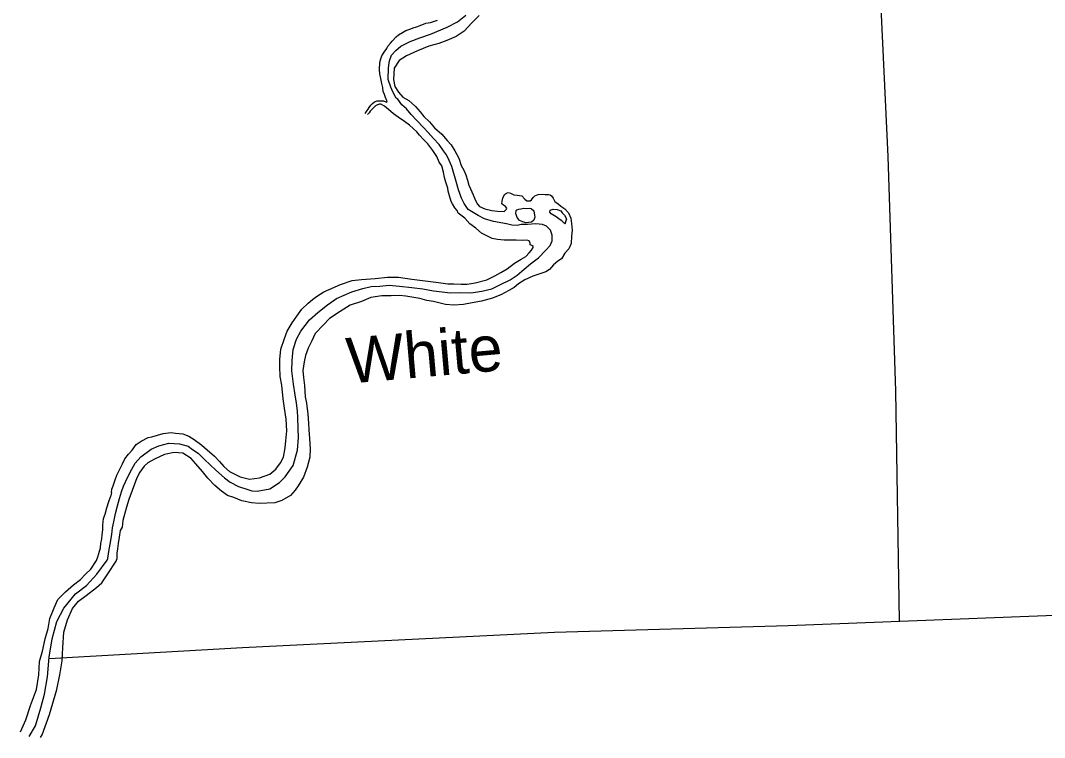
# Model space of a CAD drawing. Extents: x -939622 to -934222, y 1383701 to 1385301.
# Drawn here: x -935921.64 to -935886.1, y 1383819.87 to 1383844.76 of the extents above; entities that cross this region are included whole.
import ezdxf

# ---------------------------------------------------------------- set-up
doc = ezdxf.new("R2010")
doc.units = 0
for name, color, linetype in [('Level 2', 7, 'Continuous'), ('Level 7', 7, 'Continuous'), ('Level 9', 7, 'Continuous')]:
    doc.layers.add(name, color=color, linetype=linetype)

msp = doc.modelspace()

# ---------------------------------------------------------------- linework, layer by layer
at = {"layer": 'Level 2'}
for points in [[(-935907.297, 1383840.655), (-935907.483, 1383840.867), (-935907.641, 1383841.031), (-935907.891, 1383841.295), (-935908.08, 1383841.497), (-935908.241, 1383841.688), (-935908.398, 1383841.828), (-935908.539, 1383842.02), (-935908.594, 1383842.066), (-935908.714, 1383842.277), (-935908.782, 1383842.446), (-935908.873, 1383842.711), (-935908.869, 1383843.115), (-935908.831, 1383843.353), (-935908.759, 1383843.548), (-935908.613, 1383843.711), (-935908.431, 1383843.864), (-935908.112, 1383844.023), (-935907.777, 1383844.152), (-935907.402, 1383844.277), (-935906.824, 1383844.522), (-935906.466, 1383844.706), (-935906.185, 1383844.943)], [(-935918.608, 1383826.091), (-935918.597, 1383826.172), (-935918.568, 1383826.326), (-935918.519, 1383826.589), (-935918.468, 1383826.925), (-935918.441, 1383827.148), (-935918.393, 1383827.354), (-935918.342, 1383827.65), (-935918.271, 1383827.914), (-935918.203, 1383828.171), (-935918.129, 1383828.405), (-935918.059, 1383828.596), (-935917.912, 1383828.925), (-935917.776, 1383829.185), (-935917.653, 1383829.399), (-935917.455, 1383829.615), (-935917.102, 1383829.886), (-935916.83, 1383830.002), (-935916.487, 1383830.093), (-935916.117, 1383830.07), (-935915.821, 1383829.979), (-935915.668, 1383829.872), (-935915.475, 1383829.742), (-935915.256, 1383829.522), (-935914.862, 1383829.157), (-935914.557, 1383828.883), (-935914.358, 1383828.738), (-935914.071, 1383828.586), (-935913.744, 1383828.478), (-935913.602, 1383828.44), (-935913.428, 1383828.427), (-935912.986, 1383828.505), (-935912.644, 1383828.728), (-935912.452, 1383828.92), (-935912.175, 1383829.319), (-935912.019, 1383829.843), (-935911.983, 1383830.29), (-935912.001, 1383830.599), (-935912.011, 1383830.978), (-935912.018, 1383831.212), (-935912.058, 1383831.476), (-935912.109, 1383831.769), (-935912.161, 1383832.135), (-935912.219, 1383832.599), (-935912.208, 1383832.963), (-935912.168, 1383833.344), (-935912.052, 1383833.693), (-935911.907, 1383833.973), (-935911.609, 1383834.367), (-935911.313, 1383834.625), (-935910.981, 1383834.886), (-935910.666, 1383835.103), (-935910.133, 1383835.34), (-935909.752, 1383835.456), (-935909.466, 1383835.524), (-935909.169, 1383835.538), (-935908.846, 1383835.571), (-935908.479, 1383835.542), (-935908.058, 1383835.485), (-935907.676, 1383835.444), (-935907.305, 1383835.379), (-935907.004, 1383835.343), (-935906.721, 1383835.311), (-935906.391, 1383835.314), (-935906.012, 1383835.301), (-935905.627, 1383835.36), (-935905.284, 1383835.441), (-935905, 1383835.585), (-935904.642, 1383835.76), (-935904.394, 1383835.917), (-935904.151, 1383836.128), (-935903.94, 1383836.312), (-935903.661, 1383836.524), (-935903.402, 1383836.784), (-935903.256, 1383836.95), (-935903.186, 1383837.115), (-935903.182, 1383837.304), (-935903.241, 1383837.477), (-935903.377, 1383837.618), (-935903.523, 1383837.677), (-935903.754, 1383837.698), (-935904.036, 1383837.678), (-935904.264, 1383837.671), (-935904.404, 1383837.637), (-935904.581, 1383837.648), (-935904.768, 1383837.694), (-935905.224, 1383837.777), (-935905.536, 1383837.874), (-935905.755, 1383837.988), (-935906.097, 1383838.195), (-935906.241, 1383838.408), (-935906.336, 1383838.589), (-935906.437, 1383838.881), (-935906.511, 1383839.167), (-935906.62, 1383839.528), (-935906.67, 1383839.686), (-935906.757, 1383839.9), (-935906.846, 1383840.099), (-935906.961, 1383840.232), (-935907.102, 1383840.45), (-935907.297, 1383840.655)], [(-935921.334, 1383819.907), (-935921.12, 1383820.279), (-935920.93, 1383820.903), (-935920.805, 1383821.376), (-935920.699, 1383821.977), (-935920.64, 1383822.661), (-935920.532, 1383823.296), (-935920.371, 1383823.896), (-935920.132, 1383824.36), (-935919.732, 1383824.858), (-935919.341, 1383825.152), (-935918.982, 1383825.541), (-935918.633, 1383826.031)], [(-935918.633, 1383826.031), (-935918.608, 1383826.091)], [(-935913.934, 1383822.998), (-935903.106, 1383823.536), (-935894.989, 1383823.764), (-935875.309, 1383824.525), (-935867.115, 1383824.747)], [(-935920.644, 1383822.616), (-935913.934, 1383822.998)]]:
    msp.add_lwpolyline(points, dxfattribs=at)
at = {"layer": 'Level 7'}
msp.add_lwpolyline([(-935896.686, 1383895.228), (-935896.692, 1383895.118), (-935896.683, 1383895.013), (-935896.486, 1383887.025), (-935887.112, 1383887.354), (-935886.89, 1383879.388), (-935886.772, 1383871.452), (-935889.082, 1383871.38), (-935888.724, 1383863.988), (-935888.377, 1383856.042), (-935888.055, 1383848.114), (-935891.908, 1383847.912), (-935891.53, 1383840.037), (-935891.265, 1383831.888), (-935891.146, 1383823.913)], dxfattribs=at)
at = {"layer": 'Level 9'}
for points in [[(-935909.68, 1383841.525), (-935909.648, 1383841.565), (-935909.608, 1383841.635), (-935909.573, 1383841.681), (-935909.536, 1383841.736), (-935909.472, 1383841.816), (-935909.423, 1383841.878), (-935909.349, 1383841.931), (-935909.257, 1383841.967), (-935909.155, 1383841.97), (-935909.086, 1383841.972), (-935909.035, 1383841.964), (-935908.962, 1383841.933), (-935908.932, 1383841.925), (-935908.908, 1383841.934), (-935908.921, 1383841.976), (-935908.95, 1383842.023), (-935908.97, 1383842.089), (-935909.005, 1383842.184), (-935909.044, 1383842.292), (-935909.066, 1383842.429), (-935909.091, 1383842.567), (-935909.126, 1383842.74), (-935909.164, 1383842.905), (-935909.18, 1383843.055), (-935909.166, 1383843.296), (-935909.13, 1383843.429), (-935909.091, 1383843.533), (-935909.011, 1383843.661), (-935908.927, 1383843.778), (-935908.884, 1383843.86), (-935908.8, 1383843.968), (-935908.736, 1383844.036), (-935908.6, 1383844.19), (-935908.512, 1383844.258), (-935908.376, 1383844.34), (-935908.267, 1383844.413), (-935908.094, 1383844.466), (-935908.008, 1383844.501), (-935907.892, 1383844.54), (-935907.765, 1383844.583), (-935907.569, 1383844.658), (-935907.405, 1383844.689), (-935907.161, 1383844.768)], [(-935905.719, 1383844.928), (-935905.97, 1383844.672), (-935906.238, 1383844.385), (-935906.518, 1383844.199), (-935906.838, 1383844.061), (-935907.12, 1383843.957), (-935907.465, 1383843.863), (-935907.863, 1383843.708), (-935908.242, 1383843.535), (-935908.498, 1383843.362), (-935908.665, 1383843.102), (-935908.693, 1383842.71), (-935908.644, 1383842.465), (-935908.519, 1383842.27), (-935908.364, 1383842.1)], [(-935908.364, 1383842.1), (-935908.163, 1383841.982), (-935907.926, 1383841.772), (-935907.761, 1383841.581), (-935907.64, 1383841.425), (-935907.443, 1383841.244), (-935907.263, 1383841.029), (-935907.008, 1383840.814), (-935906.824, 1383840.596), (-935906.688, 1383840.441), (-935906.568, 1383840.237), (-935906.423, 1383839.979), (-935906.338, 1383839.723), (-935906.246, 1383839.557), (-935906.185, 1383839.399), (-935906.125, 1383839.214), (-935906.073, 1383839.047), (-935906.018, 1383838.913), (-935905.928, 1383838.708), (-935905.848, 1383838.515), (-935905.781, 1383838.384), (-935905.71, 1383838.296), (-935905.521, 1383838.223), (-935905.274, 1383838.161), (-935905.087, 1383838.139), (-935904.853, 1383838.127), (-935904.774, 1383838.208), (-935904.757, 1383838.241), (-935904.803, 1383838.297), (-935904.868, 1383838.343), (-935904.926, 1383838.393), (-935904.923, 1383838.489), (-935904.902, 1383838.592), (-935904.836, 1383838.714), (-935904.775, 1383838.761), (-935904.706, 1383838.787), (-935904.625, 1383838.768), (-935904.509, 1383838.711), (-935904.404, 1383838.693), (-935904.232, 1383838.674), (-935904.129, 1383838.55), (-935904.059, 1383838.498), (-935903.951, 1383838.498), (-935903.901, 1383838.536), (-935903.84, 1383838.613), (-935903.788, 1383838.671), (-935903.669, 1383838.714), (-935903.522, 1383838.724), (-935903.432, 1383838.723), (-935903.312, 1383838.72), (-935903.249, 1383838.707), (-935903.209, 1383838.672), (-935903.144, 1383838.593), (-935903.089, 1383838.48), (-935902.973, 1383838.396), (-935902.881, 1383838.308), (-935902.749, 1383838.222), (-935902.619, 1383838.084), (-935902.542, 1383837.894), (-935902.513, 1383837.708), (-935902.494, 1383837.483), (-935902.512, 1383837.269), (-935902.529, 1383837.016), (-935902.611, 1383836.833), (-935902.739, 1383836.682), (-935902.862, 1383836.489), (-935902.983, 1383836.407), (-935903.138, 1383836.274), (-935903.278, 1383836.111), (-935903.404, 1383836.029), (-935903.651, 1383835.953), (-935903.859, 1383835.878), (-935904.132, 1383835.759), (-935904.347, 1383835.615), (-935904.505, 1383835.49), (-935904.692, 1383835.389), (-935904.943, 1383835.249), (-935905.257, 1383835.126), (-935905.635, 1383835.019), (-935905.958, 1383834.962), (-935906.262, 1383834.903), (-935906.601, 1383834.881), (-935906.892, 1383834.906), (-935907.306, 1383835.009), (-935907.529, 1383835.045), (-935907.774, 1383835.105), (-935907.988, 1383835.138), (-935908.259, 1383835.187), (-935908.482, 1383835.211), (-935908.77, 1383835.206), (-935909.091, 1383835.198), (-935909.476, 1383835.139), (-935909.799, 1383835.003), (-935910.192, 1383834.881), (-935910.54, 1383834.655), (-935910.914, 1383834.41), (-935911.124, 1383834.191), (-935911.409, 1383833.894), (-935911.528, 1383833.638), (-935911.647, 1383833.388), (-935911.748, 1383833.136)], [(-935909.33, 1383841.784), (-935909.4, 1383841.713), (-935909.459, 1383841.66), (-935909.502, 1383841.605), (-935909.534, 1383841.556), (-935909.589, 1383841.494)], [(-935909.33, 1383841.784), (-935909.307, 1383841.806), (-935909.286, 1383841.82), (-935909.263, 1383841.834), (-935909.236, 1383841.841), (-935909.201, 1383841.854), (-935909.184, 1383841.857), (-935909.163, 1383841.858), (-935909.14, 1383841.858), (-935909.129, 1383841.854)], [(-935909.129, 1383841.854), (-935909.129, 1383841.854)], [(-935906.214, 1383837.894), (-935906.441, 1383838.068), (-935906.486, 1383838.163), (-935906.563, 1383838.251), (-935906.639, 1383838.397), (-935906.687, 1383838.477), (-935906.746, 1383838.67), (-935906.79, 1383838.838), (-935906.811, 1383838.936), (-935906.87, 1383839.142), (-935906.917, 1383839.312), (-935906.958, 1383839.492), (-935907.018, 1383839.707), (-935907.106, 1383839.837), (-935907.184, 1383840.033), (-935907.328, 1383840.249), (-935907.496, 1383840.473), (-935907.641, 1383840.61), (-935907.789, 1383840.771), (-935907.883, 1383840.892), (-935908.003, 1383841.003), (-935908.141, 1383841.122), (-935908.313, 1383841.25), (-935908.53, 1383841.406), (-935908.686, 1383841.516), (-935908.862, 1383841.668), (-935909.009, 1383841.781), (-935909.129, 1383841.854)], [(-935904.434, 1383838.166), (-935904.41, 1383838.182), (-935904.342, 1383838.214), (-935904.267, 1383838.222), (-935904.175, 1383838.242), (-935904.073, 1383838.236), (-935903.974, 1383838.245), (-935903.908, 1383838.232), (-935903.824, 1383838.15), (-935903.793, 1383838.006), (-935903.788, 1383837.931), (-935903.818, 1383837.828), (-935903.903, 1383837.763), (-935904.005, 1383837.745), (-935904.098, 1383837.739), (-935904.2, 1383837.766), (-935904.316, 1383837.82), (-935904.356, 1383837.861), (-935904.4, 1383837.923), (-935904.436, 1383838.019), (-935904.445, 1383838.051)], [(-935904.445, 1383838.051), (-935904.434, 1383838.166)], [(-935902.731, 1383837.702), (-935902.771, 1383837.722), (-935902.851, 1383837.801), (-935902.94, 1383837.861), (-935903.011, 1383837.917), (-935903.105, 1383837.977), (-935903.215, 1383838.052), (-935903.262, 1383838.099), (-935903.258, 1383838.169), (-935903.148, 1383838.208), (-935903.015, 1383838.196), (-935902.888, 1383838.149), (-935902.832, 1383838.084), (-935902.761, 1383837.996), (-935902.714, 1383837.922), (-935902.685, 1383837.847)], [(-935904.06, 1383837.133), (-935904.218, 1383837.122), (-935904.438, 1383837.134), (-935904.624, 1383837.135), (-935904.855, 1383837.135), (-935905.077, 1383837.153), (-935905.27, 1383837.189), (-935905.636, 1383837.375), (-935905.838, 1383837.544), (-935906.044, 1383837.703), (-935906.214, 1383837.894)], [(-935902.731, 1383837.702), (-935902.685, 1383837.847)], [(-935918.482, 1383828.377), (-935918.464, 1383828.492), (-935918.422, 1383828.604), (-935918.35, 1383828.814), (-935918.292, 1383828.975), (-935918.193, 1383829.191), (-935918.102, 1383829.374), (-935918.014, 1383829.548), (-935917.883, 1383829.708), (-935917.758, 1383829.85), (-935917.62, 1383830.046), (-935917.446, 1383830.153), (-935917.201, 1383830.286), (-935917.084, 1383830.305), (-935916.885, 1383830.37), (-935916.686, 1383830.43), (-935916.41, 1383830.456), (-935916.257, 1383830.433), (-935916.007, 1383830.416), (-935915.789, 1383830.329), (-935915.614, 1383830.213), (-935915.348, 1383830.022), (-935915.154, 1383829.862), (-935914.908, 1383829.643), (-935914.735, 1383829.458), (-935914.583, 1383829.282), (-935914.38, 1383829.101), (-935914.015, 1383828.916), (-935913.686, 1383828.844), (-935913.345, 1383828.889), (-935912.982, 1383829.017), (-935912.771, 1383829.188), (-935912.618, 1383829.403), (-935912.513, 1383829.607), (-935912.447, 1383829.922), (-935912.424, 1383830.175), (-935912.388, 1383830.513), (-935912.418, 1383830.927), (-935912.474, 1383831.308), (-935912.519, 1383831.625), (-935912.562, 1383832.099), (-935912.619, 1383832.405), (-935912.634, 1383832.753), (-935912.635, 1383832.988), (-935912.603, 1383833.347), (-935912.476, 1383833.726), (-935912.387, 1383833.975), (-935912.212, 1383834.269), (-935912.041, 1383834.496), (-935911.868, 1383834.733), (-935911.652, 1383834.943), (-935911.503, 1383835.071), (-935911.365, 1383835.18), (-935911.111, 1383835.34), (-935910.924, 1383835.417), (-935910.533, 1383835.597), (-935910.12, 1383835.728), (-935909.797, 1383835.771), (-935909.33, 1383835.808), (-935908.899, 1383835.85), (-935908.518, 1383835.845), (-935908.06, 1383835.78), (-935907.69, 1383835.73), (-935907.404, 1383835.695), (-935907.133, 1383835.661), (-935906.801, 1383835.622), (-935906.597, 1383835.612), (-935906.345, 1383835.604), (-935906.135, 1383835.61), (-935905.851, 1383835.651), (-935905.452, 1383835.753), (-935905.171, 1383835.893), (-935904.961, 1383836.007), (-935904.746, 1383836.142), (-935904.493, 1383836.33), (-935904.257, 1383836.471), (-935904.104, 1383836.566), (-935903.978, 1383836.699), (-935903.897, 1383836.791), (-935903.848, 1383836.874), (-935903.843, 1383836.916), (-935903.889, 1383836.945), (-935903.95, 1383836.97), (-935903.949, 1383837.033), (-935903.978, 1383837.111), (-935904.06, 1383837.133)], [(-935911.748, 1383833.136), (-935911.79, 1383832.909), (-935911.832, 1383832.613), (-935911.82, 1383832.37), (-935911.782, 1383832.085), (-935911.758, 1383831.692), (-935911.707, 1383831.476), (-935911.667, 1383831.096), (-935911.643, 1383830.786), (-935911.624, 1383830.552), (-935911.601, 1383830.246), (-935911.588, 1383829.895), (-935911.592, 1383829.603), (-935911.687, 1383829.254), (-935911.815, 1383828.908), (-935911.996, 1383828.614), (-935912.1, 1383828.458), (-935912.265, 1383828.27), (-935912.569, 1383828.096), (-935912.813, 1383828.017), (-935913.35, 1383827.993), (-935913.62, 1383828.021), (-935913.958, 1383828.09), (-935914.229, 1383828.2), (-935914.447, 1383828.272), (-935914.655, 1383828.426), (-935914.891, 1383828.621), (-935915.13, 1383828.876), (-935915.322, 1383829.111), (-935915.552, 1383829.376), (-935915.71, 1383829.552), (-935916.006, 1383829.739), (-935916.298, 1383829.77), (-935916.644, 1383829.691), (-935916.99, 1383829.534), (-935917.218, 1383829.411), (-935917.341, 1383829.287), (-935917.5, 1383829.078), (-935917.602, 1383828.889), (-935917.764, 1383828.448), (-935917.872, 1383828.132), (-935917.961, 1383827.871), (-935918.086, 1383827.401), (-935918.112, 1383827.169), (-935918.172, 1383827.056), (-935918.21, 1383826.823), (-935918.246, 1383826.612), (-935918.271, 1383826.425), (-935918.288, 1383826.274), (-935918.292, 1383826.068)], [(-935918.482, 1383828.377), (-935918.508, 1383828.232)], [(-935918.482, 1383828.377), (-935918.508, 1383828.232)], [(-935918.995, 1383826.02), (-935918.947, 1383826.144), (-935918.921, 1383826.259), (-935918.86, 1383826.454), (-935918.843, 1383826.604), (-935918.815, 1383826.771), (-935918.798, 1383826.912), (-935918.779, 1383827.078), (-935918.78, 1383827.244), (-935918.754, 1383827.47), (-935918.698, 1383827.622), (-935918.638, 1383827.84), (-935918.569, 1383828.059), (-935918.508, 1383828.232)], [(-935921.637, 1383820.074), (-935921.45, 1383820.483), (-935921.29, 1383820.989), (-935921.077, 1383821.546), (-935920.998, 1383822.05), (-935920.978, 1383822.517), (-935920.877, 1383822.868), (-935920.775, 1383823.301), (-935920.677, 1383823.659), (-935920.62, 1383824.006), (-935920.465, 1383824.374), (-935920.339, 1383824.666), (-935920.079, 1383824.929), (-935919.8, 1383825.169), (-935919.553, 1383825.359), (-935919.375, 1383825.542), (-935919.194, 1383825.721), (-935918.995, 1383826.02)], [(-935920.939, 1383819.875), (-935920.886, 1383819.963), (-935920.627, 1383820.671), (-935920.378, 1383821.541), (-935920.275, 1383822.055), (-935920.192, 1383822.53), (-935920.172, 1383822.999), (-935920.127, 1383823.536), (-935920.001, 1383823.954), (-935919.834, 1383824.347), (-935919.62, 1383824.609), (-935919.361, 1383824.802), (-935918.993, 1383825.077), (-935918.815, 1383825.242), (-935918.61, 1383825.551), (-935918.312, 1383825.995)], [(-935918.312, 1383825.995), (-935918.292, 1383826.068)]]:
    msp.add_lwpolyline(points, dxfattribs=at)

# ---------------------------------------------------------------- texts
msp.add_text('White', height=1.584, rotation=5, dxfattribs=at).set_placement((-935910.245, 1383832.154))

doc.saveas('drawing.dxf')
